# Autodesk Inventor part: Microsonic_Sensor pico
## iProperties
Shininess: 20.0
Length Units: 11269
Angle Units: 11279
Time Units: 11290
Mass Units: 11283
Length Display Precision: 2
Angle Display Precision: 2
Part Number: Microsonic_Sensor pico
Material: Nichtrostender Stahl - 440C
Document SubType Name: Modellieren
Description: pico-XXX-25/CD/X/HV/M18
Checked By: Alves
Created: 2005-08
Designer: Ohle
Manufacturer: Standard
Standards Organization: Custom
Density: 0.0
Volumn: 0.0
Area: 0.0
PropertySet Name: Model Information
Control State: 0
Master: False
Checked Out: False
Last Check In By: Kramp
Last Check In Date: 2005-08-09
BESTELLNUMMER: pico-XXX-25/CD/X/HV/M18
ME: ST
Title: pico Sensoren
Author: Ohle
Comments: keine Bemerkung
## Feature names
1. Grundkörper wms-25 [Revolution]
2. Pole [Extrusion]
3. Rundung Pole [Fillet]
4. Verdrehsicherung [Extrusion]
